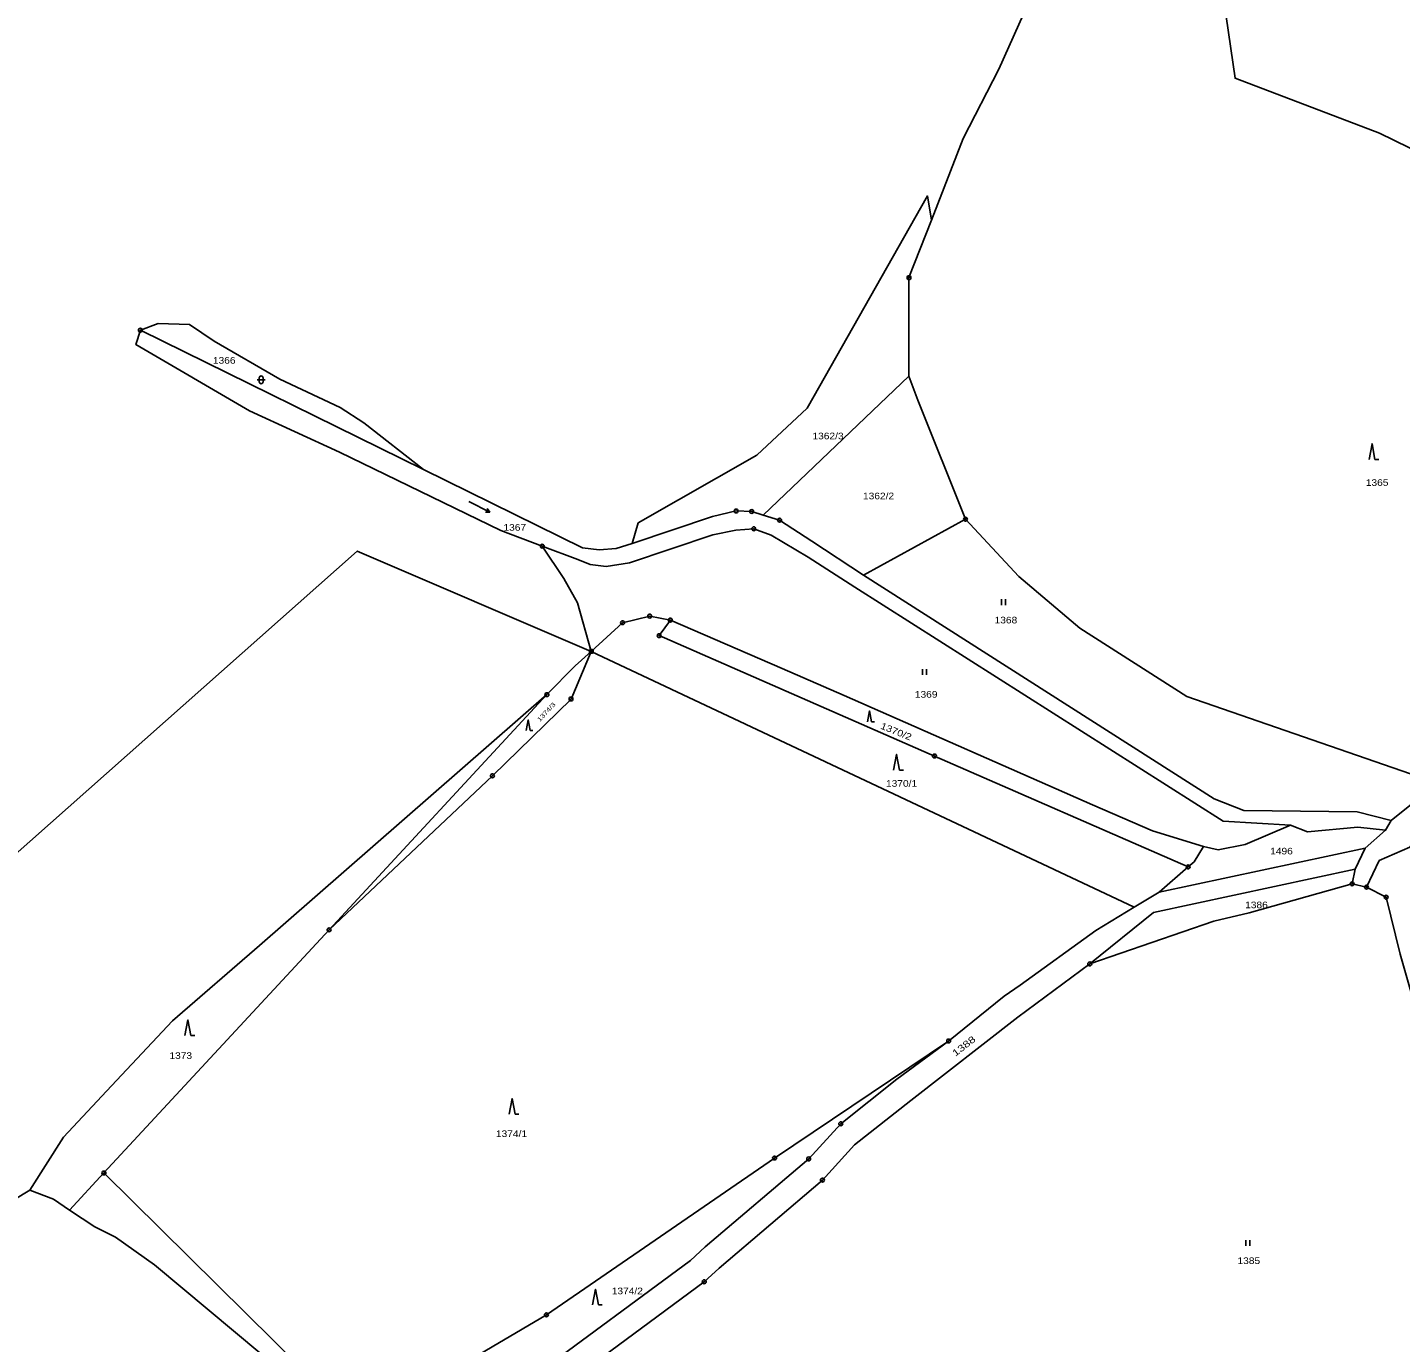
# Model space of a CAD drawing. Extents: x -872229 to -869198, y -1075981 to -1074329.
# Drawn here: x -870624.7 to -870272.3, y -1074936.4 to -1074598.7 of the extents above; entities that cross this region are included whole.
import ezdxf

# ---------------------------------------------------------------- set-up
doc = ezdxf.new("R2010")
doc.units = 0
doc.header["$LTSCALE"] = 0.68
for name, color, linetype, lineweight in [('1', 7, 'Continuous', 25), ('3', 7, 'Continuous', 25), ('8', 7, 'Continuous', 25)]:
    doc.layers.add(name, color=color, linetype=linetype, lineweight=lineweight)
doc.layers.add('2', color=7, linetype='Continuous')

msp = doc.modelspace()

# ---------------------------------------------------------------- linework, layer by layer
at = {"layer": '1'}
for p, q in [((-870595.77, -1074676.43), (-870523.11, -1074712.21)), ((-870398.48, -1074688.22), (-870435.87, -1074723.92)), ((-870383.96, -1074724.98), (-870410.13, -1074739.32)), ((-870340.65, -1074824.57), (-870480.02, -1074758.9)), ((-870274.68, -1074802.33), (-870262.81, -1074792.73)), ((-870276.13, -1074804.85), (-870281.35, -1074809.47)), ((-870281.35, -1074809.47), (-870334.23, -1074820.74)), ((-870283.91, -1074814.8), (-870281.35, -1074809.47)), ((-870284.74, -1074818.59), (-870283.91, -1074814.8)), ((-870281.03, -1074819.44), (-870284.74, -1074818.59)), ((-870334.23, -1074820.74), (-870340.65, -1074824.57))]:
    msp.add_line(p, q, dxfattribs=at)
for points in [[(-870357.04, -1074569.54), (-870364.01, -1074583.91), (-870375.37, -1074609.39), (-870384.59, -1074627.22), (-870392.73, -1074648.17)], [(-870357.04, -1074569.54), (-870334.99, -1074573.21), (-870317.65, -1074591.75), (-870314.76, -1074611.74), (-870277.71, -1074625.88), (-870247.77, -1074640.47), (-870171.77, -1074684.38), (-870155.5, -1074702.23), (-870143.77, -1074693.61)], [(-870469.5, -1074731.24), (-870467.99, -1074725.92), (-870437.54, -1074708.54), (-870424.64, -1074696.45), (-870393.74, -1074641.94), (-870392.73, -1074648.17)], [(-870392.73, -1074648.17), (-870398.47, -1074662.95), (-870398.48, -1074688.22)], [(-870523.11, -1074712.21), (-870538.43, -1074700.24), (-870544.46, -1074696.33), (-870559.97, -1074689.03), (-870576.81, -1074679.28), (-870583.11, -1074674.97), (-870591.16, -1074674.71), (-870595.77, -1074676.43)], [(-870595.77, -1074676.43), (-870596.89, -1074680.13), (-870567.73, -1074697.15), (-870544.63, -1074707.77), (-870503.26, -1074727.86), (-870492.61, -1074731.9)], [(-870398.48, -1074688.22), (-870396.18, -1074694.42), (-870383.96, -1074724.98)], [(-870469.5, -1074731.24), (-870473.67, -1074732.47), (-870478.01, -1074732.82), (-870482.28, -1074732.32), (-870523.11, -1074712.21)], [(-870435.87, -1074723.92), (-870438.85, -1074723), (-870442.83, -1074722.86), (-870448.91, -1074724.25), (-870469.5, -1074731.24)], [(-870410.13, -1074739.32), (-870423.39, -1074730.62), (-870431.69, -1074725.21), (-870435.87, -1074723.92)], [(-870492.61, -1074731.9), (-870483.48, -1074735.36), (-870480.28, -1074736.61), (-870476.19, -1074737.1), (-870470.18, -1074736.18), (-870448.8, -1074728.97), (-870442.91, -1074727.76), (-870438.31, -1074727.43), (-870433.87, -1074729.03), (-870424.37, -1074734.72), (-870412.39, -1074742.41), (-870317.81, -1074802.55), (-870300.52, -1074803.57)], [(-870383.96, -1074724.98), (-870370.29, -1074739.68), (-870354.63, -1074752.92), (-870327.13, -1074770.46), (-870262.81, -1074792.73)], [(-870480.02, -1074758.9), (-870540.11, -1074733.14), (-870634.05, -1074816.48)], [(-870492.61, -1074731.9), (-870487.04, -1074740.2), (-870483.52, -1074746.43), (-870480.02, -1074758.9)], [(-870274.68, -1074802.33), (-870283.45, -1074800.09), (-870312.56, -1074799.77), (-870320.1, -1074796.77), (-870410.13, -1074739.32)], [(-870480.02, -1074758.9), (-870471.98, -1074751.55), (-870465.03, -1074749.85), (-870459.73, -1074750.88)], [(-870326.82, -1074814.26), (-870391.95, -1074785.78), (-870462.6, -1074754.87), (-870459.73, -1074750.88)], [(-870459.73, -1074750.88), (-870431.06, -1074763.27), (-870415.11, -1074770.28), (-870351.38, -1074798.28), (-870336, -1074805), (-870322.87, -1074809.03)], [(-870480.02, -1074758.9), (-870485.22, -1074771.14), (-870505.4, -1074790.85), (-870547.32, -1074830.41)], [(-870491.42, -1074770.02), (-870484.12, -1074762.65), (-870480.02, -1074758.9)], [(-870624.12, -1074897.23), (-870615.46, -1074883.64), (-870603.15, -1074870.48), (-870587.53, -1074853.78), (-870565.21, -1074834.4), (-870491.42, -1074770.02)], [(-870613.94, -1074902.37), (-870605.12, -1074892.84), (-870547.32, -1074830.41), (-870491.42, -1074770.02)], [(-870263, -1074800.37), (-870268.38, -1074806.91), (-870269.92, -1074809.15), (-870277.75, -1074812.62), (-870281.03, -1074819.44)], [(-870322.87, -1074809.03), (-870319.14, -1074809.85), (-870312.16, -1074808.46), (-870300.52, -1074803.57)], [(-870300.52, -1074803.57), (-870296.18, -1074805.24), (-870283.23, -1074804.02), (-870276.13, -1074804.85), (-870274.68, -1074802.33)], [(-870322.87, -1074809.03), (-870325.3, -1074812.93), (-870326.82, -1074814.26), (-870334.23, -1074820.74)], [(-870283.91, -1074814.8), (-870335.75, -1074825.96), (-870352.08, -1074839.16)], [(-870284.74, -1074818.59), (-870311.17, -1074826.03), (-870320.19, -1074828.16), (-870352.08, -1074839.16)], [(-870256.59, -1074884.78), (-870263.53, -1074877.85), (-870268.59, -1074849.87), (-870272.4, -1074836.68), (-870275.99, -1074822.05), (-870281.03, -1074819.44)], [(-870340.65, -1074824.57), (-870350.55, -1074830.58), (-870369.97, -1074844.66), (-870374.04, -1074847.42), (-870388.3, -1074858.96)], [(-870352.08, -1074839.16), (-870370.51, -1074852.86), (-870398.03, -1074874.22), (-870412.45, -1074885.65), (-870420.69, -1074894.67), (-870447.23, -1074917.28), (-870451.03, -1074920.77), (-870491.11, -1074950.4), (-870524.35, -1074974.36)], [(-870605.12, -1074892.84), (-870539.63, -1074957.56), (-870491.54, -1074929.27), (-870432.98, -1074889.01), (-870388.3, -1074858.96)], [(-870388.3, -1074858.96), (-870401.56, -1074868.78), (-870415.98, -1074880.21), (-870424.22, -1074889.23), (-870450.76, -1074911.84), (-870454.56, -1074915.33), (-870494.64, -1074944.96)], [(-870823.34, -1074990.34), (-870743.76, -1074956.82), (-870646.76, -1074910.9), (-870624.12, -1074897.23)], [(-870624.12, -1074897.23), (-870618.07, -1074899.6), (-870613.94, -1074902.37)], [(-870542.19, -1074967.42), (-870543.47, -1074965.12), (-870548.12, -1074957.33), (-870555.12, -1074947.81), (-870564.62, -1074939.42), (-870592.11, -1074916.44), (-870602.17, -1074909.34), (-870607.46, -1074906.7), (-870613.94, -1074902.37)]]:
    msp.add_lwpolyline(points, dxfattribs=at)
at = {"layer": '3'}
for p, q in [((-870565.751, -1074689.181), (-870563.749, -1074689.181)), ((-870565.251, -1074688.681), (-870565.251, -1074689.682)), ((-870564.249, -1074689.682), (-870564.249, -1074688.681)), ((-870278.86, -1074709.6), (-870277.864, -1074709.6)), ((-870506.076, -1074723.127), (-870507.174, -1074723.131)), ((-870374.711, -1074747.04), (-870374.711, -1074745.54)), ((-870373.71, -1074747.04), (-870373.71, -1074745.54)), ((-870395.011, -1074764.95), (-870395.011, -1074763.45)), ((-870394.01, -1074764.95), (-870394.01, -1074763.45)), ((-870408.055, -1074776.99), (-870407.358, -1074776.99)), ((-870495.708, -1074779.19), (-870495.04, -1074779.19)), ((-870400.91, -1074789.38), (-870399.914, -1074789.38)), ((-870582.82, -1074857.56), (-870581.824, -1074857.56)), ((-870499.59, -1074877.73), (-870498.594, -1074877.73)), ((-870312.021, -1074911.56), (-870312.021, -1074910.06)), ((-870311.02, -1074911.56), (-870311.02, -1074910.06)), ((-870478.21, -1074926.72), (-870477.214, -1074926.72))]:
    msp.add_line(p, q, dxfattribs=at)
for points in [[(-870278.86, -1074709.6), (-870279.61, -1074705.6), (-870280.36, -1074709.6)], [(-870511.422, -1074720.403), (-870506.076, -1074723.127), (-870506.719, -1074722.237)], [(-870495.708, -1074779.19), (-870496.21, -1074776.51), (-870496.712, -1074779.19)], [(-870408.055, -1074776.99), (-870408.58, -1074774.19), (-870409.105, -1074776.99)], [(-870400.91, -1074789.38), (-870401.66, -1074785.38), (-870402.41, -1074789.38)], [(-870582.82, -1074857.56), (-870583.57, -1074853.56), (-870584.32, -1074857.56)], [(-870499.59, -1074877.73), (-870500.34, -1074873.73), (-870501.09, -1074877.73)], [(-870478.21, -1074926.72), (-870478.96, -1074922.72), (-870479.71, -1074926.72)]]:
    msp.add_lwpolyline(points, dxfattribs=at)
for centre, start, end in [((-870564.75, -1074688.6809), 0, 180), ((-870564.75, -1074689.6809), 180, 359.98789)]:
    msp.add_arc(centre, 0.5, start, end, dxfattribs=at)
at = {"layer": '8'}
for centre, radius in [((-870398.47, -1074662.9499), 0.5), ((-870398.47, -1074662.9499), 0.0303), ((-870595.77, -1074676.4299), 0.5), ((-870595.77, -1074676.4299), 0.0303), ((-870442.83, -1074722.8599), 0.5), ((-870442.83, -1074722.8599), 0.0303), ((-870438.85, -1074722.9999), 0.5), ((-870438.85, -1074722.9999), 0.0303), ((-870383.96, -1074724.9799), 0.5), ((-870438.31, -1074727.4299), 0.5), ((-870438.31, -1074727.4299), 0.0303), ((-870431.69, -1074725.2099), 0.5), ((-870431.69, -1074725.2099), 0.0303), ((-870383.96, -1074724.9799), 0.0303), ((-870492.61, -1074731.8999), 0.5), ((-870492.61, -1074731.8999), 0.0303), ((-870471.98, -1074751.5499), 0.5), ((-870471.98, -1074751.5499), 0.0303), ((-870465.03, -1074749.8499), 0.5), ((-870465.03, -1074749.8499), 0.0303), ((-870459.73, -1074750.8799), 0.5), ((-870459.73, -1074750.8799), 0.0303), ((-870462.6, -1074754.8699), 0.5), ((-870462.6, -1074754.8699), 0.0303), ((-870480.02, -1074758.8999), 0.5), ((-870480.02, -1074758.8999), 0.0303), ((-870491.42, -1074770.0199), 0.5), ((-870491.42, -1074770.0199), 0.0303), ((-870485.22, -1074771.1399), 0.5), ((-870485.22, -1074771.1399), 0.0303), ((-870391.95, -1074785.7799), 0.5), ((-870391.95, -1074785.7799), 0.0303), ((-870505.4, -1074790.8499), 0.5), ((-870505.4, -1074790.8499), 0.0303), ((-870326.82, -1074814.2599), 0.5), ((-870326.82, -1074814.2599), 0.0303), ((-870284.74, -1074818.5899), 0.5), ((-870284.74, -1074818.5899), 0.0303), ((-870281.03, -1074819.4399), 0.5), ((-870281.03, -1074819.4399), 0.0303), ((-870275.99, -1074822.0499), 0.5), ((-870275.99, -1074822.0499), 0.0303), ((-870547.32, -1074830.4099), 0.5), ((-870547.32, -1074830.4099), 0.0303), ((-870352.08, -1074839.1599), 0.5), ((-870352.08, -1074839.1599), 0.0303), ((-870388.3, -1074858.9599), 0.5), ((-870388.3, -1074858.9599), 0.0303), ((-870415.98, -1074880.2099), 0.5), ((-870415.98, -1074880.2099), 0.0303), ((-870432.98, -1074889.0099), 0.5), ((-870432.98, -1074889.0099), 0.0303), ((-870424.22, -1074889.2299), 0.5), ((-870424.22, -1074889.2299), 0.0303), ((-870605.12, -1074892.8399), 0.5), ((-870605.12, -1074892.8399), 0.0303), ((-870420.69, -1074894.6699), 0.5), ((-870420.69, -1074894.6699), 0.0303), ((-870451.03, -1074920.7699), 0.5), ((-870451.03, -1074920.7699), 0.0303), ((-870491.54, -1074929.2699), 0.5), ((-870491.54, -1074929.2699), 0.0303)]:
    msp.add_circle(centre, radius, dxfattribs=at)

# ---------------------------------------------------------------- texts
at = {"layer": '2', "width": 1.15}
for s, p in [('1366', (-870577.15, -1074685.04)), ('1362/3', (-870423.25, -1074704.45)), ('1365', (-870281.22, -1074716.41)), ('1362/2', (-870410.28, -1074719.85)), ('1367', (-870502.57, -1074727.93)), ('1368', (-870376.5, -1074751.73)), ('1369', (-870396.97, -1074770.8)), ('1370/1', (-870404.38, -1074793.67)), ('1496', (-870305.77, -1074811.05)), ('1386', (-870312.19, -1074824.86)), ('1373', (-870588.31, -1074863.55)), ('1374/1', (-870504.5, -1074883.61)), ('1385', (-870314.15, -1074916.22)), ('1374/2', (-870474.77, -1074923.98))]:
    msp.add_text(s, height=1.7, dxfattribs=at).set_placement(p)
at = {"layer": '2'}
for s, height, rotation, width, p in [('1374/3', 1.139, 47, 1.3, (-870493.213, -1074777.068)), ('1370/2', 1.7, 338, 1.2, (-870405.948, -1074778.698)), ('1388', 1.7, 38, 1.35, (-870386.566, -1074863.029))]:
    msp.add_text(s, height=height, rotation=rotation, dxfattribs=dict(at, width=width)).set_placement(p)

doc.saveas('drawing.dxf')
